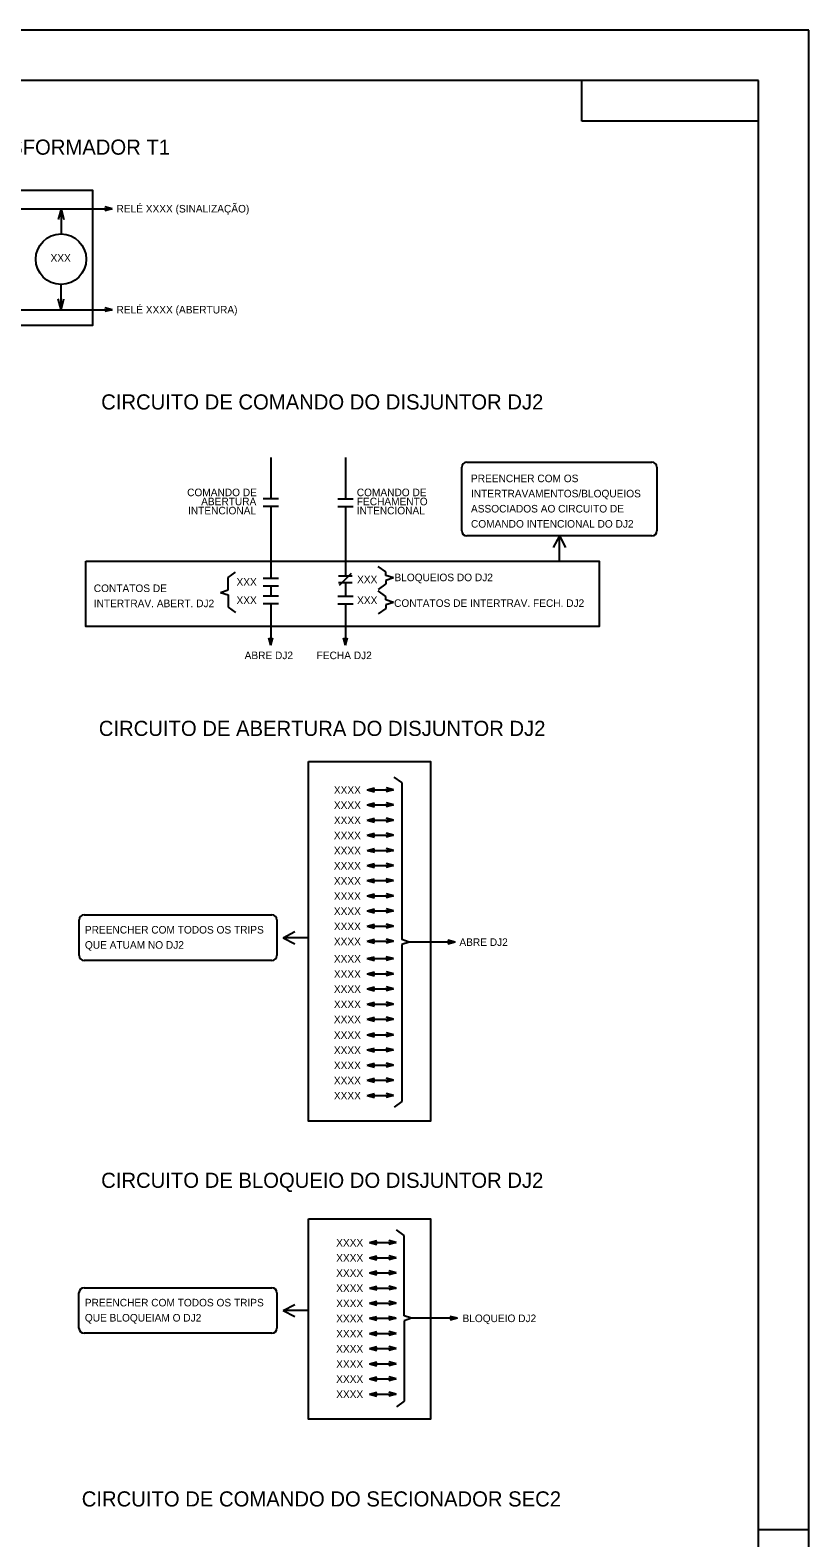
# Model space of a CAD drawing. Extents: x 563 to 1404, y 358 to 952.
# Drawn here: x 1249.3 to 1403.6, y 653.3 to 952 of the extents above; entities that cross this region are included whole.
import ezdxf

# ---------------------------------------------------------------- set-up
doc = ezdxf.new("R2010")
doc.units = 0
doc.layers.add('New Level (0)', color=7, linetype='Continuous')

# ---------------------------------------------------------------- blocks, each defined once
blk = doc.blocks.new('39')
for p, q in [((0, 0), (1.45, 0.39)), ((0, 0), (5.22, 0)), ((0, 0), (1.45, -0.39)), ((5.22, 0), (3.77, 0.39)), ((5.22, 0), (3.77, -0.39))]:
    blk.add_line(p, q)

msp = doc.modelspace()

# ---------------------------------------------------------------- linework, layer by layer
for p, q in [((1265.58, 916.59), (1264.13, 916.98)), ((1206.46, 916.59), (1265.58, 916.59)), ((1255.43, 916.59), (1254.85, 914.42)), ((1255.43, 916.59), (1255.43, 911.59)), ((1255.43, 916.59), (1256.01, 914.42)), ((1265.58, 916.59), (1264.13, 916.2)), ((1255.43, 896.59), (1255.43, 901.59)), ((1243.19, 896.59), (1265.58, 896.59)), ((1255.43, 896.59), (1254.85, 898.77)), ((1255.43, 896.59), (1256.01, 898.77)), ((1265.58, 896.59), (1264.13, 896.98)), ((1265.58, 896.59), (1264.13, 896.2)), ((1296.98, 867.28), (1296.98, 859.1)), ((1311.77, 867.28), (1311.77, 859.1)), ((1298.48, 859.1), (1295.48, 859.1)), ((1298.48, 857.6), (1295.48, 857.6)), ((1296.98, 857.6), (1296.98, 843.36)), ((1310.27, 859.1), (1313.27, 859.1)), ((1310.27, 857.6), (1313.27, 857.6)), ((1311.77, 857.6), (1311.77, 843.86)), ((1319.78, 844.64), (1318.28, 845.72)), ((1288.52, 843.55), (1290.02, 844.63)), ((1288.52, 841.08), (1288.52, 843.55)), ((1298.48, 843.36), (1295.48, 843.36)), ((1310.42, 843.86), (1313.12, 843.86)), ((1313.12, 842.51), (1310.42, 842.51)), ((1310.58, 842), (1312.97, 844.38)), ((1311.77, 842.36), (1311.77, 839.86)), ((1319.78, 842.27), (1318.28, 841.19)), ((1319.78, 843.96), (1319.78, 844.64)), ((1321.28, 843.46), (1319.78, 843.96)), ((1321.28, 843.46), (1319.78, 842.96)), ((1319.78, 842.96), (1319.78, 842.27)), ((1287.02, 840.58), (1288.52, 841.08)), ((1287.02, 840.58), (1288.52, 840.08)), ((1288.52, 840.08), (1288.52, 837.68)), ((1298.48, 841.86), (1295.48, 841.86)), ((1298.48, 839.86), (1295.48, 839.86)), ((1296.98, 841.86), (1296.98, 839.86)), ((1310.27, 839.86), (1313.27, 839.86)), ((1310.27, 839.86), (1313.27, 839.86)), ((1319.78, 839.78), (1318.28, 840.87)), ((1319.78, 839.1), (1319.78, 839.78)), ((1288.52, 837.68), (1290.02, 836.6)), ((1298.48, 838.36), (1295.48, 838.36)), ((1296.98, 838.36), (1296.98, 830.12)), ((1310.27, 838.36), (1313.27, 838.36)), ((1310.27, 838.36), (1313.27, 838.36)), ((1311.77, 838.36), (1311.77, 830.12)), ((1319.78, 837.42), (1318.28, 836.33)), ((1321.28, 838.6), (1319.78, 839.1)), ((1321.28, 838.6), (1319.78, 838.1)), ((1319.78, 838.1), (1319.78, 837.42)), ((1296.98, 830.12), (1296.59, 831.57)), ((1296.98, 830.12), (1297.37, 831.57)), ((1311.77, 830.12), (1311.38, 831.57)), ((1311.77, 830.12), (1312.16, 831.57)), ((1322.92, 802.92), (1321.42, 804)), ((1316.1, 801.5), (1317.55, 801.89)), ((1316.1, 801.5), (1321.32, 801.5)), ((1316.1, 801.5), (1317.55, 801.11)), ((1321.32, 801.5), (1319.87, 801.89)), ((1321.32, 801.5), (1319.87, 801.11)), ((1322.92, 802.92), (1322.92, 771.82)), ((1316.1, 798.5), (1317.55, 798.89)), ((1316.1, 798.5), (1321.32, 798.5)), ((1316.1, 798.5), (1317.55, 798.11)), ((1321.32, 798.5), (1319.87, 798.89)), ((1321.32, 798.5), (1319.87, 798.11)), ((1316.1, 795.5), (1317.55, 795.89)), ((1316.1, 795.5), (1321.32, 795.5)), ((1316.1, 795.5), (1317.55, 795.11)), ((1321.32, 795.5), (1319.87, 795.89)), ((1321.32, 795.5), (1319.87, 795.11)), ((1324.42, 771.32), (1322.92, 771.82)), ((1324.42, 771.32), (1322.92, 770.82)), ((1322.92, 770.82), (1322.92, 739.73)), ((1333.48, 771.32), (1324.42, 771.32)), ((1333.48, 771.32), (1332.03, 771.71)), ((1333.48, 771.32), (1332.03, 770.94)), ((1316.1, 768.06), (1317.55, 768.44)), ((1316.1, 768.06), (1321.32, 768.06)), ((1316.1, 768.06), (1317.55, 767.67)), ((1321.32, 768.06), (1319.87, 768.44)), ((1321.32, 768.06), (1319.87, 767.67)), ((1316.1, 752.96), (1317.55, 753.35)), ((1316.1, 752.96), (1321.32, 752.96)), ((1316.1, 752.96), (1317.55, 752.57)), ((1321.32, 752.96), (1319.87, 753.35)), ((1321.32, 752.96), (1319.87, 752.57)), ((1322.92, 739.73), (1321.42, 738.65)), ((1323.39, 713.23), (1321.89, 714.31)), ((1316.57, 711.81), (1318.02, 712.2)), ((1316.57, 711.81), (1321.79, 711.81)), ((1316.57, 711.81), (1318.02, 711.43)), ((1321.79, 711.81), (1320.34, 712.2)), ((1321.79, 711.81), (1320.34, 711.43)), ((1323.39, 697.31), (1323.39, 713.23)), ((1316.57, 705.81), (1318.02, 706.2)), ((1316.57, 705.81), (1321.79, 705.81)), ((1316.57, 705.81), (1318.02, 705.43)), ((1321.79, 705.81), (1320.34, 706.2)), ((1321.79, 705.81), (1320.34, 705.43)), ((1324.89, 696.81), (1323.39, 697.31)), ((1324.89, 696.81), (1323.39, 696.31)), ((1323.39, 696.31), (1323.39, 680.4)), ((1333.95, 696.81), (1324.89, 696.81)), ((1333.95, 696.81), (1332.5, 697.2)), ((1333.95, 696.81), (1332.5, 696.43)), ((1323.39, 680.4), (1321.89, 679.31))]:
    msp.add_line(p, q)
msp.add_circle((1255.43, 906.59), 5)
at = {"layer": 'New Level (0)'}
for p, q in [((1403.58, 951.96), (562.58, 951.96)), ((1403.58, 951.96), (562.58, 951.96)), ((1403.58, 357.96), (1403.58, 951.96)), ((1403.58, 357.96), (1403.58, 951.96)), ((1393.58, 941.96), (572.58, 941.96)), ((1358.58, 933.96), (1358.58, 941.96)), ((1393.58, 367.96), (1393.58, 941.96)), ((1393.58, 367.96), (1393.58, 941.96)), ((1393.58, 933.96), (1358.58, 933.96)), ((1335.83, 866.38), (1372.48, 866.38)), ((1334.83, 852.79), (1334.83, 865.38)), ((1373.48, 865.38), (1373.48, 852.79)), ((1372.48, 851.79), (1335.83, 851.79)), ((1354.15, 851.79), (1352.94, 849.49)), ((1354.15, 846.76), (1354.15, 851.79)), ((1354.15, 851.79), (1355.36, 849.49)), ((1259.99, 776.72), (1267.34, 776.72)), ((1267.34, 776.72), (1297.21, 776.72)), ((1258.99, 768.69), (1258.99, 775.72)), ((1298.21, 775.72), (1298.21, 768.69)), ((1299.45, 772.2), (1301.75, 773.41)), ((1304.48, 772.2), (1299.45, 772.2)), ((1299.45, 772.2), (1301.75, 770.99)), ((1297.21, 767.69), (1259.99, 767.69)), ((1258.98, 694.84), (1258.98, 701.87)), ((1259.98, 702.87), (1267.33, 702.87)), ((1267.33, 702.87), (1297.21, 702.87)), ((1298.21, 701.87), (1298.21, 694.84)), ((1299.45, 698.36), (1301.74, 699.57)), ((1304.48, 698.36), (1299.45, 698.36)), ((1299.45, 698.36), (1301.74, 697.15)), ((1297.21, 693.84), (1259.98, 693.84)), ((1393.58, 654.96), (1403.58, 654.96))]:
    msp.add_line(p, q, dxfattribs=at)
for points in [[(1197.77, 920.29), (1261.69, 920.29), (1261.69, 893.47), (1197.77, 893.47)], [(1260.35, 846.76), (1362.05, 846.76), (1362.05, 833.87), (1260.35, 833.87)], [(1304.48, 807.12), (1328.61, 807.12), (1328.61, 735.87), (1304.48, 735.87)], [(1304.48, 716.5), (1328.61, 716.5), (1328.61, 676.86), (1304.48, 676.86)]]:
    msp.add_lwpolyline(points, close=True, dxfattribs=at)
for centre, start, end in [((1335.83, 865.38), 90, 180), ((1372.48, 865.38), 0, 90), ((1335.83, 852.79), 180, 270), ((1372.48, 852.79), 270, 0), ((1259.99, 775.72), 90, 180), ((1297.21, 775.72), 0, 90), ((1259.99, 768.69), 180, 270), ((1297.21, 768.69), 270, 0), ((1259.98, 701.87), 90, 180), ((1297.21, 701.87), 0, 90), ((1259.98, 694.84), 180, 270), ((1297.21, 694.84), 270, 0)]:
    msp.add_arc(centre, 1, start, end, dxfattribs=at)

# ---------------------------------------------------------------- block references
for p in [(1316.1, 792.5), (1316.1, 789.5), (1316.1, 786.5), (1316.1, 783.5), (1316.1, 780.5), (1316.1, 777.5), (1316.1, 774.5), (1316.1, 771.5), (1316.1, 765.06), (1316.1, 762.06), (1316.1, 759.06), (1316.1, 756.06), (1316.1, 749.96), (1316.1, 746.96), (1316.1, 743.96), (1316.1, 740.96), (1316.57, 708.81), (1316.57, 702.81), (1316.57, 699.81), (1316.57, 696.81), (1316.57, 693.81), (1316.57, 690.81), (1316.57, 687.81), (1316.57, 684.81), (1316.57, 681.81)]:
    msp.add_blockref('39', p)

# ---------------------------------------------------------------- texts
for s, height, p in [('SINALIZAÇÃO TRANSFORMADOR T1', 3, (1206.59, 927.29)), ('RELÉ XXXX (SINALIZAÇÃO)', 1.5, (1266.42, 915.84)), ('XXX', 1.5, (1253.35, 906.09)), ('RELÉ XXXX (ABERTURA)', 1.5, (1266.42, 895.84)), ('CIRCUITO DE COMANDO DO DISJUNTOR DJ2', 3, (1263.38, 876.82)), ('PREENCHER COM OS ', 1.5, (1336.64, 862.42)), ('COMANDO DE', 1.5, (1280.41, 859.65)), ('COMANDO DE ', 1.5, (1314.02, 859.65)), ('INTERTRAVAMENTOS/BLOQUEIOS', 1.5, (1336.64, 859.42)), (' INTENCIONAL', 1.5, (1280.03, 856.05)), (' ABERTURA', 1.5, (1282.63, 857.85)), ('FECHAMENTO ', 1.5, (1314.02, 857.85)), ('INTENCIONAL', 1.5, (1314.02, 856.05)), ('ASSOCIADOS AO CIRCUITO DE ', 1.5, (1336.64, 856.42)), ('COMANDO INTENCIONAL DO DJ2', 1.5, (1336.64, 853.42)), ('CONTATOS DE ', 1.5, (1261.92, 840.66)), ('XXX', 1.5, (1290.19, 841.92)), ('XXX', 1.5, (1314.08, 842.41)), ('BLOQUEIOS DO DJ2', 1.5, (1321.48, 842.81)), ('INTERTRAV. ABERT. DJ2', 1.5, (1261.92, 837.66)), ('XXX', 1.5, (1290.19, 838.29)), ('XXX', 1.5, (1314.08, 838.29)), ('CONTATOS DE INTERTRAV. FECH. DJ2', 1.5, (1321.41, 837.72)), ('ABRE DJ2', 1.5, (1291.8, 827.37)), ('FECHA DJ2', 1.5, (1306.07, 827.37)), ('CIRCUITO DE ABERTURA DO DISJUNTOR DJ2', 3, (1262.91, 812.16)), ('XXXX', 1.5, (1309.48, 800.7)), ('XXXX', 1.5, (1309.48, 797.7)), ('XXXX', 1.5, (1309.48, 794.7)), ('XXXX', 1.5, (1309.48, 791.7)), ('XXXX', 1.5, (1309.48, 788.7)), ('XXXX', 1.5, (1309.48, 785.7)), ('XXXX', 1.5, (1309.48, 782.7)), ('XXXX', 1.5, (1309.48, 779.7)), ('XXXX', 1.5, (1309.48, 776.7)), ('PREENCHER COM TODOS OS TRIPS', 1.5, (1260.16, 773.02)), ('XXXX', 1.5, (1309.48, 773.7)), ('QUE ATUAM NO DJ2', 1.5, (1260.16, 770.02)), ('XXXX', 1.5, (1309.48, 770.7)), ('ABRE DJ2', 1.5, (1334.35, 770.57)), ('XXXX', 1.5, (1309.48, 767.26)), ('XXXX', 1.5, (1309.48, 764.26)), ('XXXX', 1.5, (1309.48, 761.26)), ('XXXX', 1.5, (1309.48, 758.26)), ('XXXX', 1.5, (1309.48, 755.26)), ('XXXX', 1.5, (1309.48, 752.16)), ('XXXX', 1.5, (1309.48, 749.16)), ('XXXX', 1.5, (1309.48, 746.16)), ('XXXX', 1.5, (1309.48, 743.16)), ('XXXX', 1.5, (1309.48, 740.16)), ('CIRCUITO DE BLOQUEIO DO DISJUNTOR DJ2', 3, (1263.38, 722.65)), ('XXXX', 1.5, (1309.94, 711.02)), ('XXXX', 1.5, (1309.94, 708.02)), ('XXXX', 1.5, (1309.94, 705.02)), ('XXXX', 1.5, (1309.94, 702.02)), ('PREENCHER COM TODOS OS TRIPS', 1.5, (1260.15, 699.17)), ('XXXX', 1.5, (1309.94, 699.02)), ('QUE BLOQUEIAM O DJ2', 1.5, (1260.15, 696.17)), ('XXXX', 1.5, (1309.94, 696.02)), ('BLOQUEIO DJ2', 1.5, (1334.96, 696.06)), ('XXXX', 1.5, (1309.94, 693.02)), ('XXXX', 1.5, (1309.94, 690.02)), ('XXXX', 1.5, (1309.94, 687.02)), ('XXXX', 1.5, (1309.94, 684.02)), ('XXXX', 1.5, (1309.94, 681.02)), ('CIRCUITO DE COMANDO DO SECIONADOR SEC2', 3, (1259.53, 659.54))]:
    msp.add_text(s, height=height).set_placement(p)

doc.saveas('drawing.dxf')
